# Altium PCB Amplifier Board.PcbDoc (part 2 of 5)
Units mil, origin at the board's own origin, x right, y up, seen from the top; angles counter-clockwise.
Board outline 6000 x 4000 mil, 6 copper layers (Top Layer, GND, VCC, InternalPlane3, InternalPlane4, Bottom Layer); 880 components, 519 nets, 2020 pads, 372 vias.
Unrouted connection lines stored in the file: 585.
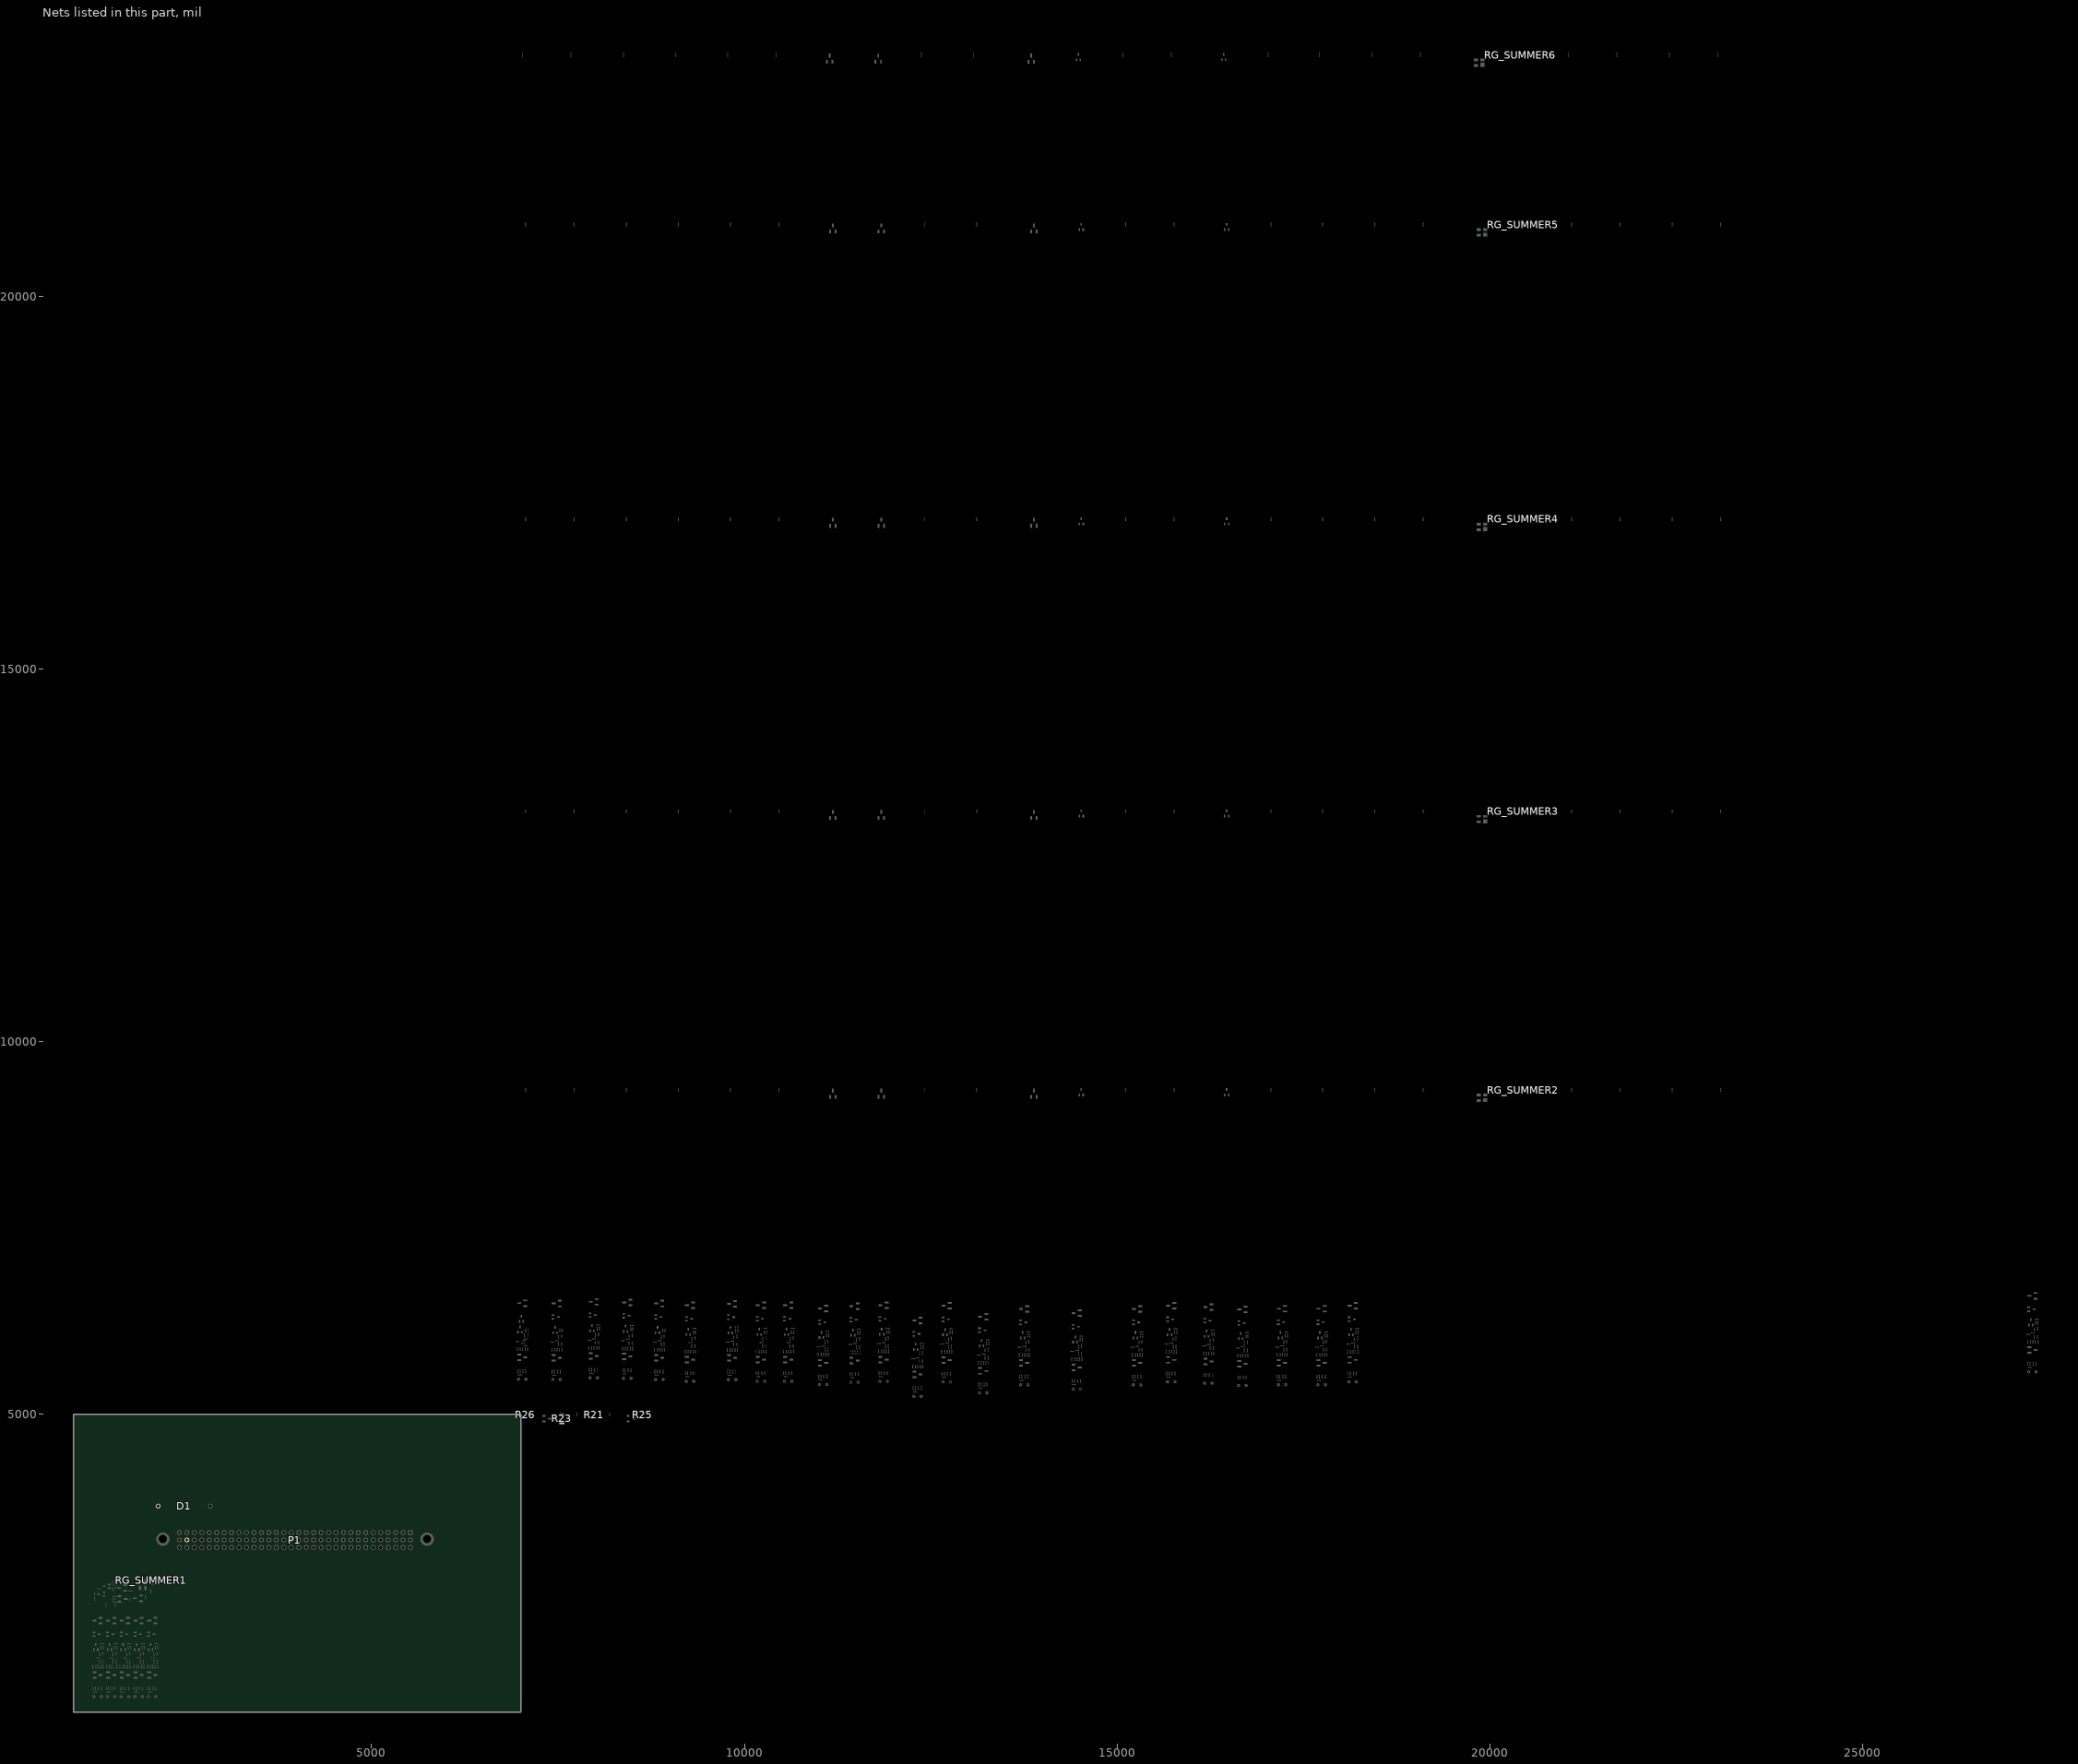
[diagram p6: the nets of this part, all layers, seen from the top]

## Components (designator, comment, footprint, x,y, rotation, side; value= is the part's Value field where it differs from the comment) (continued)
R2_AMP3 "Res2" RESC0603L 1715,1679 r90 top (schematic designator R2)
R2_AMP4 "Res2" RESC0603L 1899,1679 r90 top (schematic designator R2)
R2_AMP5 "Res2" RESC0603L 2082,1679 r90 top (schematic designator R2)
R2_AMP6 "Res2" RESC0603L 7030,5950 r0 top (schematic designator R2)
R2_AMP7 "Res2" RESC0603L 7507,5934 r90 top (schematic designator R2)
R2_AMP8 "Res2" RESC0603L 8004,5958 r90 top (schematic designator R2)
R2_AMP9 "Res2" RESC0603L 8455,5951 r90 top (schematic designator R2)
R2_AMP10 "Res2" RESC0603L 8884,5934 r90 top (schematic designator R2)
R2_AMP11 "Res2" RESC0603L 9296,5910 r90 top (schematic designator R2)
R2_AMP12 "Res2" RESC0603L 9860,5932 r90 top (schematic designator R2)
R2_AMP13 "Res2" RESC0603L 10247,5910 r90 top (schematic designator R2)
R2_AMP14 "Res2" RESC0603L 10613,5910 r90 top (schematic designator R2)
R2_AMP15 "Res2" RESC0603L 11081,5867 r90 top (schematic designator R2)
R2_AMP16 "Res2" RESC0603L 11503,5899 r90 top (schematic designator R2)
R2_AMP17 "Res2" RESC0603L 11891,5911 r90 top (schematic designator R2)
R2_AMP18 "Res2" RESC0603L 12347,5709 r90 top (schematic designator R2)
R2_AMP19 "Res2" RESC0603L 12739,5905 r90 top (schematic designator R2)
R2_AMP20 "Res2" RESC0603L 13229,5758 r90 top (schematic designator R2)
R2_AMP21 "Res2" RESC0603L 13779,5864 r90 top (schematic designator R2)
R2_AMP22 "Res2" RESC0603L 14484,5806 r90 top (schematic designator R2)
R2_AMP23 "Res2" RESC0603L 15293,5864 r90 top (schematic designator R2)
R2_AMP24 "Res2" RESC0603L 15751,5906 r90 top (schematic designator R2)
R2_AMP25 "Res2" RESC0603L 16250,5885 r90 top (schematic designator R2)
R2_AMP26 "Res2" RESC0603L 16707,5854 r90 top (schematic designator R2)
R2_AMP27 "Res2" RESC0603L 17237,5865 r90 top (schematic designator R2)
R2_AMP28 "Res2" RESC0603L 17768,5865 r90 top (schematic designator R2)
R2_AMP29 "Res2" RESC0603L 18185,5906 r90 top (schematic designator R2)
R2_AMP30 "Res2" RESC0603L 27303,6038 r90 top (schematic designator R2)
R3_AMP1 "Res2" RESC0603L 1264,1714 r0 top (schematic designator R3)
R3_AMP2 "Res2" RESC0603L 1447,1714 r0 top (schematic designator R3)
R3_AMP3 "Res2" RESC0603L 1630,1714 r0 top (schematic designator R3)
R3_AMP4 "Res2" RESC0603L 1814,1714 r0 top (schematic designator R3)
R3_AMP5 "Res2" RESC0603L 1997,1714 r0 top (schematic designator R3)
R3_AMP6 "Res2" RESC0603L 6960,5974 r0 top (schematic designator R3)
R3_AMP7 "Res2" RESC0603L 7422,5969 r0 top (schematic designator R3)
R3_AMP8 "Res2" RESC0603L 7919,5993 r0 top (schematic designator R3)
R3_AMP9 "Res2" RESC0603L 8370,5986 r0 top (schematic designator R3)
R3_AMP10 "Res2" RESC0603L 8799,5969 r0 top (schematic designator R3)
R3_AMP11 "Res2" RESC0603L 9211,5945 r0 top (schematic designator R3)
R3_AMP12 "Res2" RESC0603L 9775,5967 r0 top (schematic designator R3)
R3_AMP13 "Res2" RESC0603L 10162,5945 r0 top (schematic designator R3)
R3_AMP14 "Res2" RESC0603L 10528,5945 r0 top (schematic designator R3)
R3_AMP15 "Res2" RESC0603L 10996,5902 r0 top (schematic designator R3)
R3_AMP16 "Res2" RESC0603L 11418,5934 r0 top (schematic designator R3)
R3_AMP17 "Res2" RESC0603L 11806,5946 r0 top (schematic designator R3)
R3_AMP18 "Res2" RESC0603L 12262,5744 r0 top (schematic designator R3)
R3_AMP19 "Res2" RESC0603L 12654,5940 r0 top (schematic designator R3)
R3_AMP20 "Res2" RESC0603L 13144,5793 r0 top (schematic designator R3)
R3_AMP21 "Res2" RESC0603L 13694,5899 r0 top (schematic designator R3)
R3_AMP22 "Res2" RESC0603L 14399,5841 r0 top (schematic designator R3)
R3_AMP23 "Res2" RESC0603L 15208,5899 r0 top (schematic designator R3)
R3_AMP24 "Res2" RESC0603L 15666,5941 r0 top (schematic designator R3)
R3_AMP25 "Res2" RESC0603L 16165,5920 r0 top (schematic designator R3)
R3_AMP26 "Res2" RESC0603L 16622,5889 r0 top (schematic designator R3)
R3_AMP27 "Res2" RESC0603L 17152,5900 r0 top (schematic designator R3)
R3_AMP28 "Res2" RESC0603L 17683,5900 r0 top (schematic designator R3)
R3_AMP29 "Res2" RESC0603L 18100,5941 r0 top (schematic designator R3)
R3_AMP30 "Res2" RESC0603L 27218,6073 r0 top (schematic designator R3)
R4_AMP1 "Res2" RESC0603L 1329,1729 r0 top (schematic designator R4)
R4_AMP2 "Res2" RESC0603L 1512,1729 r0 top (schematic designator R4)
R4_AMP3 "Res2" RESC0603L 1695,1729 r0 top (schematic designator R4)
R4_AMP4 "Res2" RESC0603L 1879,1729 r0 top (schematic designator R4)
R4_AMP5 "Res2" RESC0603L 2062,1729 r0 top (schematic designator R4)
R4_AMP6 "Res2" RESC0603L 7040,5988 r0 top (schematic designator R4)
R4_AMP7 "Res2" RESC0603L 7487,5984 r0 top (schematic designator R4)
R4_AMP8 "Res2" RESC0603L 7984,6008 r0 top (schematic designator R4)
R4_AMP9 "Res2" RESC0603L 8435,6001 r0 top (schematic designator R4)
R4_AMP10 "Res2" RESC0603L 8864,5984 r0 top (schematic designator R4)
R4_AMP11 "Res2" RESC0603L 9276,5960 r0 top (schematic designator R4)
R4_AMP12 "Res2" RESC0603L 9840,5982 r0 top (schematic designator R4)
R4_AMP13 "Res2" RESC0603L 10227,5960 r0 top (schematic designator R4)
R4_AMP14 "Res2" RESC0603L 10593,5960 r0 top (schematic designator R4)
R4_AMP15 "Res2" RESC0603L 11061,5917 r0 top (schematic designator R4)
R4_AMP16 "Res2" RESC0603L 11483,5949 r0 top (schematic designator R4)
R4_AMP17 "Res2" RESC0603L 11871,5961 r0 top (schematic designator R4)
R4_AMP18 "Res2" RESC0603L 12327,5759 r0 top (schematic designator R4)
R4_AMP19 "Res2" RESC0603L 12719,5955 r0 top (schematic designator R4)
R4_AMP20 "Res2" RESC0603L 13209,5808 r0 top (schematic designator R4)
R4_AMP21 "Res2" RESC0603L 13759,5914 r0 top (schematic designator R4)
R4_AMP22 "Res2" RESC0603L 14464,5856 r0 top (schematic designator R4)
R4_AMP23 "Res2" RESC0603L 15273,5914 r0 top (schematic designator R4)
R4_AMP24 "Res2" RESC0603L 15731,5956 r0 top (schematic designator R4)
R4_AMP25 "Res2" RESC0603L 16230,5935 r0 top (schematic designator R4)
R4_AMP26 "Res2" RESC0603L 16687,5904 r0 top (schematic designator R4)
R4_AMP27 "Res2" RESC0603L 17217,5915 r0 top (schematic designator R4)
R4_AMP28 "Res2" RESC0603L 17748,5915 r0 top (schematic designator R4)
R4_AMP29 "Res2" RESC0603L 18165,5956 r0 top (schematic designator R4)
R4_AMP30 "Res2" RESC0603L 27283,6088 r0 top (schematic designator R4)
R5_AMP1 "Res2" RESC0603L 1349,1779 r270 top (schematic designator R5)
R5_AMP2 "Res2" RESC0603L 1532,1779 r270 top (schematic designator R5)
R5_AMP3 "Res2" RESC0603L 1715,1779 r270 top (schematic designator R5)
R5_AMP4 "Res2" RESC0603L 1899,1779 r270 top (schematic designator R5)
R5_AMP5 "Res2" RESC0603L 2082,1779 r270 top (schematic designator R5)
R5_AMP6 "Res2" RESC0603L 7065,6013 r0 top (schematic designator R5)
R5_AMP7 "Res2" RESC0603L 7507,6034 r270 top (schematic designator R5)
R5_AMP8 "Res2" RESC0603L 8004,6058 r270 top (schematic designator R5)
R5_AMP9 "Res2" RESC0603L 8455,6051 r270 top (schematic designator R5)
R5_AMP10 "Res2" RESC0603L 8884,6034 r270 top (schematic designator R5)
R5_AMP11 "Res2" RESC0603L 9296,6010 r270 top (schematic designator R5)
R5_AMP12 "Res2" RESC0603L 9860,6032 r270 top (schematic designator R5)
R5_AMP13 "Res2" RESC0603L 10247,6010 r270 top (schematic designator R5)
R5_AMP14 "Res2" RESC0603L 10613,6010 r270 top (schematic designator R5)
R5_AMP15 "Res2" RESC0603L 11081,5967 r270 top (schematic designator R5)
R5_AMP16 "Res2" RESC0603L 11503,5999 r270 top (schematic designator R5)
R5_AMP17 "Res2" RESC0603L 11891,6011 r270 top (schematic designator R5)
R5_AMP18 "Res2" RESC0603L 12347,5809 r270 top (schematic designator R5)
R5_AMP19 "Res2" RESC0603L 12739,6005 r270 top (schematic designator R5)
R5_AMP20 "Res2" RESC0603L 13229,5858 r270 top (schematic designator R5)
R5_AMP21 "Res2" RESC0603L 13779,5964 r270 top (schematic designator R5)
R5_AMP22 "Res2" RESC0603L 14484,5906 r270 top (schematic designator R5)
R5_AMP23 "Res2" RESC0603L 15293,5964 r270 top (schematic designator R5)
R5_AMP24 "Res2" RESC0603L 15751,6006 r270 top (schematic designator R5)
R5_AMP25 "Res2" RESC0603L 16250,5985 r270 top (schematic designator R5)
R5_AMP26 "Res2" RESC0603L 16707,5954 r270 top (schematic designator R5)
R5_AMP27 "Res2" RESC0603L 17237,5965 r270 top (schematic designator R5)
R5_AMP28 "Res2" RESC0603L 17768,5965 r270 top (schematic designator R5)
R5_AMP29 "Res2" RESC0603L 18185,6006 r270 top (schematic designator R5)
R5_AMP30 "Res2" RESC0603L 27303,6138 r270 top (schematic designator R5)
R6_AMP1 "Res2" RESC0603L 1363,1610 r90 top (schematic designator R6)
R6_AMP2 "Res2" RESC0603L 1546,1610 r90 top (schematic designator R6)
R6_AMP3 "Res2" RESC0603L 1729,1610 r90 top (schematic designator R6)
R6_AMP4 "Res2" RESC0603L 1913,1610 r90 top (schematic designator R6)
R6_AMP5 "Res2" RESC0603L 2096,1610 r90 top (schematic designator R6)
R6_AMP6 "Res2" RESC0603L 7059,5870 r90 top (schematic designator R6)
R6_AMP7 "Res2" RESC0603L 7521,5865 r90 top (schematic designator R6)
R6_AMP8 "Res2" RESC0603L 8018,5889 r90 top (schematic designator R6)
R6_AMP9 "Res2" RESC0603L 8469,5882 r90 top (schematic designator R6)
R6_AMP10 "Res2" RESC0603L 8898,5865 r90 top (schematic designator R6)
R6_AMP11 "Res2" RESC0603L 9310,5841 r90 top (schematic designator R6)
R6_AMP12 "Res2" RESC0603L 9874,5863 r90 top (schematic designator R6)
R6_AMP13 "Res2" RESC0603L 10261,5841 r90 top (schematic designator R6)
R6_AMP14 "Res2" RESC0603L 10627,5841 r90 top (schematic designator R6)
R6_AMP15 "Res2" RESC0603L 11095,5798 r90 top (schematic designator R6)
R6_AMP16 "Res2" RESC0603L 11517,5830 r90 top (schematic designator R6)
R6_AMP17 "Res2" RESC0603L 11905,5842 r90 top (schematic designator R6)
R6_AMP18 "Res2" RESC0603L 12361,5640 r90 top (schematic designator R6)
R6_AMP19 "Res2" RESC0603L 12753,5836 r90 top (schematic designator R6)
R6_AMP20 "Res2" RESC0603L 13243,5689 r90 top (schematic designator R6)
R6_AMP21 "Res2" RESC0603L 13793,5795 r90 top (schematic designator R6)
R6_AMP22 "Res2" RESC0603L 14498,5737 r90 top (schematic designator R6)
R6_AMP23 "Res2" RESC0603L 15307,5795 r90 top (schematic designator R6)
R6_AMP24 "Res2" RESC0603L 15765,5837 r90 top (schematic designator R6)
R6_AMP25 "Res2" RESC0603L 16264,5816 r90 top (schematic designator R6)
R6_AMP26 "Res2" RESC0603L 16721,5785 r90 top (schematic designator R6)
R6_AMP27 "Res2" RESC0603L 17251,5796 r90 top (schematic designator R6)
R6_AMP28 "Res2" RESC0603L 17782,5796 r90 top (schematic designator R6)
R6_AMP29 "Res2" RESC0603L 18199,5837 r90 top (schematic designator R6)
R6_AMP30 "Res2" RESC0603L 27317,5969 r90 top (schematic designator R6)
R7_AMP1 "Res2" RESC0603L 1389,1789 r270 top (schematic designator R7)
R7_AMP2 "Res2" RESC0603L 1572,1789 r270 top (schematic designator R7)
R7_AMP3 "Res2" RESC0603L 1755,1789 r270 top (schematic designator R7)
R7_AMP4 "Res2" RESC0603L 1939,1789 r270 top (schematic designator R7)
R7_AMP5 "Res2" RESC0603L 2122,1789 r270 top (schematic designator R7)
R7_AMP6 "Res2" RESC0603L 7095,6058 r270 top (schematic designator R7)
R7_AMP7 "Res2" RESC0603L 7547,6044 r270 top (schematic designator R7)
R7_AMP8 "Res2" RESC0603L 8044,6068 r270 top (schematic designator R7)
R7_AMP9 "Res2" RESC0603L 8495,6061 r270 top (schematic designator R7)
R7_AMP10 "Res2" RESC0603L 8924,6044 r270 top (schematic designator R7)
R7_AMP11 "Res2" RESC0603L 9336,6020 r270 top (schematic designator R7)
R7_AMP12 "Res2" RESC0603L 9900,6042 r270 top (schematic designator R7)
R7_AMP13 "Res2" RESC0603L 10287,6020 r270 top (schematic designator R7)
R7_AMP14 "Res2" RESC0603L 10653,6020 r270 top (schematic designator R7)
R7_AMP15 "Res2" RESC0603L 11121,5977 r270 top (schematic designator R7)
R7_AMP16 "Res2" RESC0603L 11543,6009 r270 top (schematic designator R7)
R7_AMP17 "Res2" RESC0603L 11931,6021 r270 top (schematic designator R7)
R7_AMP18 "Res2" RESC0603L 12387,5819 r270 top (schematic designator R7)
R7_AMP19 "Res2" RESC0603L 12779,6015 r270 top (schematic designator R7)
R7_AMP20 "Res2" RESC0603L 13269,5868 r270 top (schematic designator R7)
R7_AMP21 "Res2" RESC0603L 13819,5974 r270 top (schematic designator R7)
R7_AMP22 "Res2" RESC0603L 14524,5916 r270 top (schematic designator R7)
R7_AMP23 "Res2" RESC0603L 15333,5974 r270 top (schematic designator R7)
R7_AMP24 "Res2" RESC0603L 15791,6016 r270 top (schematic designator R7)
R7_AMP25 "Res2" RESC0603L 16290,5995 r270 top (schematic designator R7)
R7_AMP26 "Res2" RESC0603L 16747,5964 r270 top (schematic designator R7)
R7_AMP27 "Res2" RESC0603L 17277,5975 r270 top (schematic designator R7)
R7_AMP28 "Res2" RESC0603L 17808,5975 r270 top (schematic designator R7)
R7_AMP29 "Res2" RESC0603L 18225,6016 r270 top (schematic designator R7)
R7_AMP30 "Res2" RESC0603L 27343,6148 r270 top (schematic designator R7)
R8_AMP1 "Res2" RESC0603L 1383,1919 r180 top (schematic designator R8)
R8_AMP2 "Res2" RESC0603L 1566,1919 r180 top (schematic designator R8)
R8_AMP3 "Res2" RESC0603L 1749,1919 r180 top (schematic designator R8)
R8_AMP4 "Res2" RESC0603L 1933,1919 r180 top (schematic designator R8)
R8_AMP5 "Res2" RESC0603L 2116,1919 r180 top (schematic designator R8)
R8_AMP6 "Res2" RESC0603L 7065,6123 r270 top (schematic designator R8)
R8_AMP7 "Res2" RESC0603L 7541,6174 r180 top (schematic designator R8)
R8_AMP8 "Res2" RESC0603L 8038,6198 r180 top (schematic designator R8)
R8_AMP9 "Res2" RESC0603L 8489,6191 r180 top (schematic designator R8)
R8_AMP10 "Res2" RESC0603L 8918,6174 r180 top (schematic designator R8)
R8_AMP11 "Res2" RESC0603L 9330,6150 r180 top (schematic designator R8)
R8_AMP12 "Res2" RESC0603L 9894,6172 r180 top (schematic designator R8)
R8_AMP13 "Res2" RESC0603L 10281,6150 r180 top (schematic designator R8)
R8_AMP14 "Res2" RESC0603L 10647,6150 r180 top (schematic designator R8)
R8_AMP15 "Res2" RESC0603L 11115,6107 r180 top (schematic designator R8)
R8_AMP16 "Res2" RESC0603L 11537,6139 r180 top (schematic designator R8)
R8_AMP17 "Res2" RESC0603L 11925,6151 r180 top (schematic designator R8)
R8_AMP18 "Res2" RESC0603L 12381,5949 r180 top (schematic designator R8)
R8_AMP19 "Res2" RESC0603L 12773,6145 r180 top (schematic designator R8)
R8_AMP20 "Res2" RESC0603L 13263,5998 r180 top (schematic designator R8)
R8_AMP21 "Res2" RESC0603L 13813,6104 r180 top (schematic designator R8)
R8_AMP22 "Res2" RESC0603L 14518,6046 r180 top (schematic designator R8)
R8_AMP23 "Res2" RESC0603L 15327,6104 r180 top (schematic designator R8)
R8_AMP24 "Res2" RESC0603L 15785,6146 r180 top (schematic designator R8)
R8_AMP25 "Res2" RESC0603L 16284,6125 r180 top (schematic designator R8)
R8_AMP26 "Res2" RESC0603L 16741,6094 r180 top (schematic designator R8)
R8_AMP27 "Res2" RESC0603L 17271,6105 r180 top (schematic designator R8)
R8_AMP28 "Res2" RESC0603L 17802,6105 r180 top (schematic designator R8)
R8_AMP29 "Res2" RESC0603L 18219,6146 r180 top (schematic designator R8)
R8_AMP30 "Res2" RESC0603L 27337,6278 r180 top (schematic designator R8)
R9_SUMMER1 "Res2" RESC0603L 1435,2440 r270 top (schematic designator R9)
R9_SUMMER2 "Res2" RESC0603L 7065,9350 r90 top (schematic designator R9)
R9_SUMMER3 "Res2" RESC0603L 7065,13090 r90 top (schematic designator R9)
R9_SUMMER4 "Res2" RESC0603L 7065,17010 r90 top (schematic designator R9)
R9_SUMMER5 "Res2" RESC0603L 7065,20960 r90 top (schematic designator R9)
R9_SUMMER6 "Res2" RESC0603L 7026,23238 r90 top (schematic designator R9)
R10_SUMMER1 "Res2" RESC0603L 2035,2625 r270 top (schematic designator R10)
R10_SUMMER2 "Res2" RESC0603L 23095,9350 r90 top (schematic designator R10)
R10_SUMMER3 "Res2" RESC0603L 23095,13090 r90 top (schematic designator R10)
R10_SUMMER4 "Res2" RESC0603L 23095,17010 r90 top (schematic designator R10)
R10_SUMMER5 "Res2" RESC0603L 23095,20960 r90 top (schematic designator R10)
R10_SUMMER6 "Res2" RESC0603L 23056,23238 r90 top (schematic designator R10)
R11_SUMMER1 "Res2" RESC0603L 1760,2505 r90 top (schematic designator R11)
R11_SUMMER2 "Res2" RESC0603L 17065,9350 r90 top (schematic designator R11)
R11_SUMMER3 "Res2" RESC0603L 17065,13090 r90 top (schematic designator R11)
R11_SUMMER4 "Res2" RESC0603L 17065,17010 r90 top (schematic designator R11)
R11_SUMMER5 "Res2" RESC0603L 17065,20960 r90 top (schematic designator R11)
R11_SUMMER6 "Res2" RESC0603L 17026,23238 r90 top (schematic designator R11)
R12_SUMMER1 "Res2" RESC0603L 1550,2485 r0 top (schematic designator R12)
R12_SUMMER2 "Res2" RESC0603L 7715,9350 r90 top (schematic designator R12)
R12_SUMMER3 "Res2" RESC0603L 7715,13090 r90 top (schematic designator R12)
R12_SUMMER4 "Res2" RESC0603L 7715,17010 r90 top (schematic designator R12)
R12_SUMMER5 "Res2" RESC0603L 7715,20960 r90 top (schematic designator R12)
R12_SUMMER6 "Res2" RESC0603L 7676,23238 r90 top (schematic designator R12)
R13_SUMMER1 "Res2" RESC0603L 1559,2747 r90 top (schematic designator R13)
R13_SUMMER2 "Res2" RESC0603L 17755,9350 r90 top (schematic designator R13)
R13_SUMMER3 "Res2" RESC0603L 17755,13090 r90 top (schematic designator R13)
R13_SUMMER4 "Res2" RESC0603L 17755,17010 r90 top (schematic designator R13)
R13_SUMMER5 "Res2" RESC0603L 17755,20960 r90 top (schematic designator R13)
R13_SUMMER6 "Res2" RESC0603L 17716,23238 r90 top (schematic designator R13)
R14_SUMMER1 "Res2" RESC0603L 1764,2702 r180 top (schematic designator R14)
R14_SUMMER2 "Res2" RESC0603L 9115,9350 r90 top (schematic designator R14)
R14_SUMMER3 "Res2" RESC0603L 9115,13090 r90 top (schematic designator R14)
R14_SUMMER4 "Res2" RESC0603L 9115,17010 r90 top (schematic designator R14)
R14_SUMMER5 "Res2" RESC0603L 9115,20960 r90 top (schematic designator R14)
R14_SUMMER6 "Res2" RESC0603L 9076,23238 r90 top (schematic designator R14)
R15_SUMMER1 "Res2" RESC0603L 1345,2655 r180 top (schematic designator R15)
R15_SUMMER2 "Res2" RESC0603L 19105,9350 r90 top (schematic designator R15)
R15_SUMMER3 "Res2" RESC0603L 19105,13090 r90 top (schematic designator R15)
R15_SUMMER4 "Res2" RESC0603L 19105,17010 r90 top (schematic designator R15)
R15_SUMMER5 "Res2" RESC0603L 19105,20960 r90 top (schematic designator R15)
R15_SUMMER6 "Res2" RESC0603L 19066,23238 r90 top (schematic designator R15)
R16_SUMMER1 "Res2" RESC0603L 1285,2585 r90 top (schematic designator R16)
R16_SUMMER2 "Res2" RESC0603L 21745,9350 r90 top (schematic designator R16)
R16_SUMMER3 "Res2" RESC0603L 21745,13090 r90 top (schematic designator R16)
R16_SUMMER4 "Res2" RESC0603L 21745,17010 r90 top (schematic designator R16)
R16_SUMMER5 "Res2" RESC0603L 21745,20960 r90 top (schematic designator R16)
R16_SUMMER6 "Res2" RESC0603L 21706,23238 r90 top (schematic designator R16)
R17_SUMMER1 "Res2" RESC0603L 1764,2627 r180 top (schematic designator R17)
R17_SUMMER2 "Res2" RESC0603L 8415,9350 r90 top (schematic designator R17)
R17_SUMMER3 "Res2" RESC0603L 8415,13090 r90 top (schematic designator R17)
R17_SUMMER4 "Res2" RESC0603L 8415,17010 r90 top (schematic designator R17)
R17_SUMMER5 "Res2" RESC0603L 8415,20960 r90 top (schematic designator R17)
R17_SUMMER6 "Res2" RESC0603L 8376,23238 r90 top (schematic designator R17)
R18_AMP1 "Res2" RESC0603L 1374,1317.78 r90 top (schematic designator R18)
R18_AMP2 "Res2" RESC0603L 1557,1317.78 r90 top (schematic designator R18)
R18_AMP3 "Res2" RESC0603L 1740,1317.78 r90 top (schematic designator R18)
R18_AMP4 "Res2" RESC0603L 1924,1317.78 r90 top (schematic designator R18)
R18_AMP5 "Res2" RESC0603L 2107,1317.78 r90 top (schematic designator R18)
R18_AMP6 "Res2" RESC0603L 7070,5577.78 r90 top (schematic designator R18)
R18_AMP7 "Res2" RESC0603L 7532,5572.78 r90 top (schematic designator R18)
R18_AMP8 "Res2" RESC0603L 8029,5596.78 r90 top (schematic designator R18)
R18_AMP9 "Res2" RESC0603L 8480,5589.78 r90 top (schematic designator R18)
R18_AMP10 "Res2" RESC0603L 8909,5572.78 r90 top (schematic designator R18)
R18_AMP11 "Res2" RESC0603L 9321,5548.78 r90 top (schematic designator R18)
R18_AMP12 "Res2" RESC0603L 9885,5570.78 r90 top (schematic designator R18)
R18_AMP13 "Res2" RESC0603L 10272,5548.78 r90 top (schematic designator R18)
R18_AMP14 "Res2" RESC0603L 10638,5548.78 r90 top (schematic designator R18)
R18_AMP15 "Res2" RESC0603L 11106,5505.78 r90 top (schematic designator R18)
R18_AMP16 "Res2" RESC0603L 11528,5537.78 r90 top (schematic designator R18)
R18_AMP17 "Res2" RESC0603L 11916,5549.78 r90 top (schematic designator R18)
R18_AMP18 "Res2" RESC0603L 12372,5347.78 r90 top (schematic designator R18)
R18_AMP19 "Res2" RESC0603L 12764,5543.78 r90 top (schematic designator R18)
R18_AMP20 "Res2" RESC0603L 13254,5396.78 r90 top (schematic designator R18)
R18_AMP21 "Res2" RESC0603L 13804,5502.78 r90 top (schematic designator R18)
R18_AMP22 "Res2" RESC0603L 14509,5444.78 r90 top (schematic designator R18)
R18_AMP23 "Res2" RESC0603L 15318,5502.78 r90 top (schematic designator R18)
R18_AMP24 "Res2" RESC0603L 15776,5544.78 r90 top (schematic designator R18)
R18_AMP25 "Res2" RESC0603L 16275,5523.78 r90 top (schematic designator R18)
R18_AMP26 "Res2" RESC0603L 16732,5492.78 r90 top (schematic designator R18)
R18_AMP27 "Res2" RESC0603L 17262,5503.78 r90 top (schematic designator R18)
R18_AMP28 "Res2" RESC0603L 17793,5503.78 r90 top (schematic designator R18)
R18_AMP29 "Res2" RESC0603L 18210,5544.78 r90 top (schematic designator R18)
R18_AMP30 "Res2" RESC0603L 27328,5676.78 r90 top (schematic designator R18)
R19_AMP1 "Res2" RESC0603L 1289,1269 r180 top (schematic designator R19)
R19_AMP2 "Res2" RESC0603L 1472,1269 r180 top (schematic designator R19)
R19_AMP3 "Res2" RESC0603L 1655,1269 r180 top (schematic designator R19)
R19_AMP4 "Res2" RESC0603L 1839,1269 r180 top (schematic designator R19)
R19_AMP5 "Res2" RESC0603L 2022,1269 r180 top (schematic designator R19)
R19_AMP6 "Res2" RESC0603L 6985,5529 r180 top (schematic designator R19)
R19_AMP7 "Res2" RESC0603L 7447,5524 r180 top (schematic designator R19)
R19_AMP8 "Res2" RESC0603L 7944,5548 r180 top (schematic designator R19)
R19_AMP9 "Res2" RESC0603L 8395,5541 r180 top (schematic designator R19)
R19_AMP10 "Res2" RESC0603L 8824,5524 r180 top (schematic designator R19)
R19_AMP11 "Res2" RESC0603L 9236,5500 r180 top (schematic designator R19)
R19_AMP12 "Res2" RESC0603L 9800,5522 r180 top (schematic designator R19)
R19_AMP13 "Res2" RESC0603L 10187,5500 r180 top (schematic designator R19)
R19_AMP14 "Res2" RESC0603L 10553,5500 r180 top (schematic designator R19)
R19_AMP15 "Res2" RESC0603L 11021,5457 r180 top (schematic designator R19)
R19_AMP16 "Res2" RESC0603L 11443,5489 r180 top (schematic designator R19)
R19_AMP17 "Res2" RESC0603L 11831,5501 r180 top (schematic designator R19)
R19_AMP18 "Res2" RESC0603L 12287,5299 r180 top (schematic designator R19)
R19_AMP19 "Res2" RESC0603L 12679,5495 r180 top (schematic designator R19)
R19_AMP20 "Res2" RESC0603L 13169,5348 r180 top (schematic designator R19)
R19_AMP21 "Res2" RESC0603L 13719,5454 r180 top (schematic designator R19)
R19_AMP22 "Res2" RESC0603L 14424,5396 r180 top (schematic designator R19)
R19_AMP23 "Res2" RESC0603L 15233,5454 r180 top (schematic designator R19)
R19_AMP24 "Res2" RESC0603L 15691,5496 r180 top (schematic designator R19)
R19_AMP25 "Res2" RESC0603L 16190,5475 r180 top (schematic designator R19)
R19_AMP26 "Res2" RESC0603L 16647,5444 r180 top (schematic designator R19)
R19_AMP27 "Res2" RESC0603L 17177,5455 r180 top (schematic designator R19)
R19_AMP28 "Res2" RESC0603L 17708,5455 r180 top (schematic designator R19)
R19_AMP29 "Res2" RESC0603L 18125,5496 r180 top (schematic designator R19)
R19_AMP30 "Res2" RESC0603L 27243,5628 r180 top (schematic designator R19)
R20_AMP1 "Res2" RESC0603L 1389,1679 r90 top (schematic designator R20)
R20_AMP2 "Res2" RESC0603L 1572,1679 r90 top (schematic designator R20)
R20_AMP3 "Res2" RESC0603L 1755,1679 r90 top (schematic designator R20)
R20_AMP4 "Res2" RESC0603L 1939,1679 r90 top (schematic designator R20)
R20_AMP5 "Res2" RESC0603L 2122,1679 r90 top (schematic designator R20)
R20_AMP6 "Res2" RESC0603L 7071.22,5915 r180 top (schematic designator R20)
R20_AMP7 "Res2" RESC0603L 7547,5934 r90 top (schematic designator R20)
R20_AMP8 "Res2" RESC0603L 8044,5958 r90 top (schematic designator R20)
R20_AMP9 "Res2" RESC0603L 8495,5951 r90 top (schematic designator R20)
R20_AMP10 "Res2" RESC0603L 8924,5934 r90 top (schematic designator R20)
R20_AMP11 "Res2" RESC0603L 9336,5910 r90 top (schematic designator R20)
R20_AMP12 "Res2" RESC0603L 9900,5932 r90 top (schematic designator R20)
R20_AMP13 "Res2" RESC0603L 10287,5910 r90 top (schematic designator R20)
R20_AMP14 "Res2" RESC0603L 10653,5910 r90 top (schematic designator R20)
R20_AMP15 "Res2" RESC0603L 11121,5867 r90 top (schematic designator R20)
R20_AMP16 "Res2" RESC0603L 11543,5899 r90 top (schematic designator R20)
R20_AMP17 "Res2" RESC0603L 11931,5911 r90 top (schematic designator R20)
R20_AMP18 "Res2" RESC0603L 12387,5709 r90 top (schematic designator R20)
R20_AMP19 "Res2" RESC0603L 12779,5905 r90 top (schematic designator R20)
R20_AMP20 "Res2" RESC0603L 13269,5758 r90 top (schematic designator R20)
R20_AMP21 "Res2" RESC0603L 13819,5864 r90 top (schematic designator R20)
R20_AMP22 "Res2" RESC0603L 14524,5806 r90 top (schematic designator R20)
R20_AMP23 "Res2" RESC0603L 15333,5864 r90 top (schematic designator R20)
R20_AMP24 "Res2" RESC0603L 15791,5906 r90 top (schematic designator R20)
R20_AMP25 "Res2" RESC0603L 16290,5885 r90 top (schematic designator R20)
R20_AMP26 "Res2" RESC0603L 16747,5854 r90 top (schematic designator R20)
R20_AMP27 "Res2" RESC0603L 17277,5865 r90 top (schematic designator R20)
R20_AMP28 "Res2" RESC0603L 17808,5865 r90 top (schematic designator R20)
R20_AMP29 "Res2" RESC0603L 18225,5906 r90 top (schematic designator R20)
R20_AMP30 "Res2" RESC0603L 27343,6038 r90 top (schematic designator R20)
R21 "Res2" RESC0603L 7985,4995 r90 top
R22 "Res2" RESC0603L 8195,4995 r90 top
R23 "Res2" RESC3216L 7555,4940 r90 top
R24 "Res2" RESC0603L 7755,4995 r90 top
R25 "Res2" RESC0603L 8635,4995 r90 top
R26 "Res2" RESC0603L 7065,4995 r90 top
RBi_AMP1 "Res2" RESC0603L 1299,1610 r270 top (schematic designator RBi)
RBi_AMP2 "Res2" RESC0603L 1482,1610 r270 top (schematic designator RBi)
RBi_AMP3 "Res2" RESC0603L 1665,1610 r270 top (schematic designator RBi)
RBi_AMP4 "Res2" RESC0603L 1849,1610 r270 top (schematic designator RBi)
RBi_AMP5 "Res2" RESC0603L 2032,1610 r270 top (schematic designator RBi)
RBi_AMP6 "Res2" RESC0603L 6995,5870 r270 top (schematic designator RBi)
RBi_AMP7 "Res2" RESC0603L 7457,5865 r270 top (schematic designator RBi)
RBi_AMP8 "Res2" RESC0603L 7954,5889 r270 top (schematic designator RBi)
RBi_AMP9 "Res2" RESC0603L 8405,5882 r270 top (schematic designator RBi)
RBi_AMP10 "Res2" RESC0603L 8834,5865 r270 top (schematic designator RBi)
RBi_AMP11 "Res2" RESC0603L 9246,5841 r270 top (schematic designator RBi)
RBi_AMP12 "Res2" RESC0603L 9810,5863 r270 top (schematic designator RBi)
RBi_AMP13 "Res2" RESC0603L 10197,5841 r270 top (schematic designator RBi)
RBi_AMP14 "Res2" RESC0603L 10563,5841 r270 top (schematic designator RBi)
RBi_AMP15 "Res2" RESC0603L 11031,5798 r270 top (schematic designator RBi)
RBi_AMP16 "Res2" RESC0603L 11453,5830 r270 top (schematic designator RBi)
RBi_AMP17 "Res2" RESC0603L 11841,5842 r270 top (schematic designator RBi)
RBi_AMP18 "Res2" RESC0603L 12297,5640 r270 top (schematic designator RBi)
RBi_AMP19 "Res2" RESC0603L 12689,5836 r270 top (schematic designator RBi)
RBi_AMP20 "Res2" RESC0603L 13179,5689 r270 top (schematic designator RBi)
RBi_AMP21 "Res2" RESC0603L 13729,5795 r270 top (schematic designator RBi)
RBi_AMP22 "Res2" RESC0603L 14434,5737 r270 top (schematic designator RBi)
RBi_AMP23 "Res2" RESC0603L 15243,5795 r270 top (schematic designator RBi)
RBi_AMP24 "Res2" RESC0603L 15701,5837 r270 top (schematic designator RBi)
RBi_AMP25 "Res2" RESC0603L 16200,5816 r270 top (schematic designator RBi)
RBi_AMP26 "Res2" RESC0603L 16657,5785 r270 top (schematic designator RBi)
RBi_AMP27 "Res2" RESC0603L 17187,5796 r270 top (schematic designator RBi)
RBi_AMP28 "Res2" RESC0603L 17718,5796 r270 top (schematic designator RBi)
RBi_AMP29 "Res2" RESC0603L 18135,5837 r270 top (schematic designator RBi)
RBi_AMP30 "Res2" RESC0603L 27253,5969 r270 top (schematic designator RBi)
RBi_SUMMER1 "Res2" RESC0603L 1550,2520 r0 top (schematic designator RBi)
RBi_SUMMER2 "Res2" RESC0603L 12415,9350 r90 top (schematic designator RBi)
RBi_SUMMER3 "Res2" RESC0603L 12415,13090 r90 top (schematic designator RBi)
RBi_SUMMER4 "Res2" RESC0603L 12415,17010 r90 top (schematic designator RBi)
RBi_SUMMER5 "Res2" RESC0603L 12415,20960 r90 top (schematic designator RBi)
RBi_SUMMER6 "Res2" RESC0603L 12376,23238 r90 top (schematic designator RBi)
RC_SUMMER1 "Res2" RESC0603L 1524,2652 r90 top (schematic designator RC)
RC_SUMMER2 "Res2" RESC0603L 9815,9350 r90 top (schematic designator RC)
RC_SUMMER3 "Res2" RESC0603L 9815,13090 r90 top (schematic designator RC)
RC_SUMMER4 "Res2" RESC0603L 9815,17010 r90 top (schematic designator RC)
RC_SUMMER5 "Res2" RESC0603L 9815,20960 r90 top (schematic designator RC)
RC_SUMMER6 "Res2" RESC0603L 9776,23238 r90 top (schematic designator RC)
RD_SUMMER1 "Res2" RESC0603L 1524,2737 r90 top (schematic designator RD)
RD_SUMMER2 "Res2" RESC0603L 18455,9350 r90 top (schematic designator RD)
RD_SUMMER3 "Res2" RESC0603L 18455,13090 r90 top (schematic designator RD)
RD_SUMMER4 "Res2" RESC0603L 18455,17010 r90 top (schematic designator RD)
RD_SUMMER5 "Res2" RESC0603L 18455,20960 r90 top (schematic designator RD)
RD_SUMMER6 "Res2" RESC0603L 18416,23238 r90 top (schematic designator RD)
RG_SUMMER1 "Res2" RESC0603L 2040,2770 r90 top (schematic designator RG)
RG_SUMMER2 "Res2" RESC0603L 20445,9350 r90 top (schematic designator RG)
RG_SUMMER3 "Res2" RESC0603L 20445,13090 r90 top (schematic designator RG)
RG_SUMMER4 "Res2" RESC0603L 20445,17010 r90 top (schematic designator RG)
RG_SUMMER5 "Res2" RESC0603L 20445,20960 r90 top (schematic designator RG)
RG_SUMMER6 "Res2" RESC0603L 20406,23238 r90 top (schematic designator RG)
SIPM_AMP1 "Photo Sen" "Photonique SiPM" 1324,1159 r0 top (schematic designator SIPM)
SIPM_AMP2 "Photo Sen" "Photonique SiPM" 1507,1159 r0 top (schematic designator SIPM)
SIPM_AMP3 "Photo Sen" "Photonique SiPM" 1690,1159 r0 top (schematic designator SIPM)
SIPM_AMP4 "Photo Sen" "Photonique SiPM" 1874,1159 r0 top (schematic designator SIPM)
SIPM_AMP5 "Photo Sen" "Photonique SiPM" 2057,1159 r0 top (schematic designator SIPM)
SIPM_AMP6 "Photo Sen" "Photonique SiPM" 7020,5419 r0 top (schematic designator SIPM)
SIPM_AMP7 "Photo Sen" "Photonique SiPM" 7482,5414 r0 top (schematic designator SIPM)
SIPM_AMP8 "Photo Sen" "Photonique SiPM" 7979,5438 r0 top (schematic designator SIPM)
SIPM_AMP9 "Photo Sen" "Photonique SiPM" 8430,5431 r0 top (schematic designator SIPM)
SIPM_AMP10 "Photo Sen" "Photonique SiPM" 8859,5414 r0 top (schematic designator SIPM)
SIPM_AMP11 "Photo Sen" "Photonique SiPM" 9271,5390 r0 top (schematic designator SIPM)
SIPM_AMP12 "Photo Sen" "Photonique SiPM" 9835,5412 r0 top (schematic designator SIPM)
SIPM_AMP13 "Photo Sen" "Photonique SiPM" 10222,5390 r0 top (schematic designator SIPM)
SIPM_AMP14 "Photo Sen" "Photonique SiPM" 10588,5390 r0 top (schematic designator SIPM)
SIPM_AMP15 "Photo Sen" "Photonique SiPM" 11056,5347 r0 top (schematic designator SIPM)
SIPM_AMP16 "Photo Sen" "Photonique SiPM" 11478,5379 r0 top (schematic designator SIPM)
SIPM_AMP17 "Photo Sen" "Photonique SiPM" 11866,5391 r0 top (schematic designator SIPM)
SIPM_AMP18 "Photo Sen" "Photonique SiPM" 12322,5189 r0 top (schematic designator SIPM)
SIPM_AMP19 "Photo Sen" "Photonique SiPM" 12714,5385 r0 top (schematic designator SIPM)
SIPM_AMP20 "Photo Sen" "Photonique SiPM" 13204,5238 r0 top (schematic designator SIPM)
SIPM_AMP21 "Photo Sen" "Photonique SiPM" 13754,5344 r0 top (schematic designator SIPM)
SIPM_AMP22 "Photo Sen" "Photonique SiPM" 14459,5286 r0 top (schematic designator SIPM)
SIPM_AMP23 "Photo Sen" "Photonique SiPM" 15268,5344 r0 top (schematic designator SIPM)
SIPM_AMP24 "Photo Sen" "Photonique SiPM" 15726,5386 r0 top (schematic designator SIPM)
SIPM_AMP25 "Photo Sen" "Photonique SiPM" 16225,5365 r0 top (schematic designator SIPM)
SIPM_AMP26 "Photo Sen" "Photonique SiPM" 16682,5334 r0 top (schematic designator SIPM)
SIPM_AMP27 "Photo Sen" "Photonique SiPM" 17212,5345 r0 top (schematic designator SIPM)
SIPM_AMP28 "Photo Sen" "Photonique SiPM" 17743,5345 r0 top (schematic designator SIPM)
SIPM_AMP29 "Photo Sen" "Photonique SiPM" 18160,5386 r0 top (schematic designator SIPM)
SIPM_AMP30 "Photo Sen" "Photonique SiPM" 27278,5518 r0 top (schematic designator SIPM)
VR1 "Volt Reg" SOT23_L 8480,4940 r0 top
VR2 "Volt Reg" SOT23_L 7350,4940 r0 top

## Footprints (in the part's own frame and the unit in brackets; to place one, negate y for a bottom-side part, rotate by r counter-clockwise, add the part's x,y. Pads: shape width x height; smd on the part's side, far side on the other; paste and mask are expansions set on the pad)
DIODE-0.7 [mm] "Zener Diode; 2 Leads"
  round 1.65 hole 1: 1(-8.89,0) 2(8.89,0)
  silkscreen extent -7.37,-2.54 7.37,2.54
EURO2.54-2V96 [mm] "Connector; DIN 41612, Type C, Thru-Hole; Rows a+b+c, 96 Position; Vertical"
  round 4.6 hole 2.8: 33(-45,-0.3) 34(45,-0.3)
  rect 1.65x1.65 hole 1: A1(-39.37,-2.54)
  round 1.65 hole 1: A2(-36.83,-2.54) A3(-34.29,-2.54) A4(-31.75,-2.54) A5(-29.21,-2.54) A6(-26.67,-2.54) A7(-24.13,-2.54) A8(-21.59,-2.54) A9(-19.05,-2.54) A10(-16.51,-2.54) A11(-13.97,-2.54) A12(-11.43,-2.54) A13(-8.89,-2.54) A14(-6.35,-2.54) A15(-3.81,-2.54) A16(-1.27,-2.54) A17(1.27,-2.54) A18(3.81,-2.54) A19(6.35,-2.54) A20(8.89,-2.54) A21(11.43,-2.54) A22(13.97,-2.54) A23(16.51,-2.54) A24(19.05,-2.54) A25(21.59,-2.54) A26(24.13,-2.54) A27(26.67,-2.54) A28(29.21,-2.54) A29(31.75,-2.54) A30(34.29,-2.54) A31(36.83,-2.54) A32(39.37,-2.54) B1(-39.37,0) B2(-36.83,0) B3(-34.29,0) B4(-31.75,0) B5(-29.21,0) B6(-26.67,0) B7(-24.13,0) B8(-21.59,0) B9(-19.05,0) B10(-16.51,0) B11(-13.97,0) B12(-11.43,0) B13(-8.89,0) B14(-6.35,0) B15(-3.81,0) B16(-1.27,0) B17(1.27,0) B18(3.81,0) B19(6.35,0) B20(8.89,0) B21(11.43,0) B22(13.97,0) B23(16.51,0) B24(19.05,0) B25(21.59,0) B26(24.13,0) B27(26.67,0) B28(29.21,0) B29(31.75,0) B30(34.29,0) B31(36.83,0) B32(39.37,0) C1(-39.37,2.54) C2(-36.83,2.54) C3(-34.29,2.54) C4(-31.75,2.54) C5(-29.21,2.54) C6(-26.67,2.54) C7(-24.13,2.54) C8(-21.59,2.54) C9(-19.05,2.54) C10(-16.51,2.54) C11(-13.97,2.54) C12(-11.43,2.54) C13(-8.89,2.54) C14(-6.35,2.54) C15(-3.81,2.54) C16(-1.27,2.54) C17(1.27,2.54) C18(3.81,2.54) C19(6.35,2.54) C20(8.89,2.54) C21(11.43,2.54) C22(13.97,2.54) C23(16.51,2.54) C24(19.05,2.54) C25(21.59,2.54) C26(24.13,2.54) C27(26.67,2.54) C28(29.21,2.54) C29(31.75,2.54) C30(34.29,2.54) C31(36.83,2.54) C32(39.37,2.54)
  silkscreen extent -47.5,-5.55 47.5,5.55
"Photonique SiPM" [mil]
  round 40 hole 19.7: 1(-50,50) 2(50,50)
RESC0603L [mm] "Chip Resistor, Body 0.6x0.3mm, IPC High Density"
  rect 0.5x0.3 smd: 1(-0.35,0) 2(0.35,0)
  body extent -0.32,-0.17 0.32,0.17, height 0.3
RESC3216L [mm] "Chip Resistor, Body 3.2x1.6mm, IPC High Density"
  rect 1.1x1.7 smd: 1(-1.35,0) 2(1.35,0)
  silkscreen extent -0.4,-0.75 0.4,0.75, body extent -1.68,-0.87 1.68,0.87, height 0.71
SOT23_L [mm] "SOT23, 3-Leads, Body 2.9x1.3mm, Pitch 0.95mm, Lead Span 2.3mm, IPC High Density"
  rect 1x0.6 smd: 1(-1,0.95) 2(-1,-0.95) 3(1,0)
  silkscreen extent -1.12,-1.5 0.7,1.92, body extent -0.7,-1.5 0.7,1.5, height 1.1
SOT23_N [mm] "SOT23, 3-Leads, Body 2.9x1.3mm, Pitch 0.95mm, Lead Span 2.3mm, IPC Medium Density"
  rect 1.3x0.6 smd: 1(-1.05,0.95) 2(-1.05,-0.95) 3(1.05,0)
  silkscreen extent -1.17,-1.5 0.7,1.92, body extent -0.7,-1.5 0.7,1.5, height 1.1
SOT323_L [mm] "SOT323, 3-Leads, Body 2.0x1.3mm, Pitch 0.65mm, Lead Span 2.1mm, IPC High Density"
  rect 0.9x0.5 smd: 1(-0.9,0.65) 2(-0.9,-0.65) 3(0.9,0)
  silkscreen extent -1.02,-1.1 0.7,1.57, body extent -0.7,-1.1 0.7,1.1, height 1.1
SOT-143 [mm] "SOT-143; 4 Leads; Body 3 x 2.6 mm, inc. leads (LxW max)"
  rect 1.35x1.35 smd: 1(-0.75,-1.1)
  rect 0.9x1.35 smd: 2(0.95,-1.1) 3(0.95,1.1) 4(-0.95,1.1)
  silkscreen extent -1.88,-2.22 1.75,0.7

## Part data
C1_AMP1 C1_AMP2 C1_AMP3 C1_AMP4 C1_AMP5 C1_AMP6 C1_AMP7 C1_AMP8 C1_AMP9 C1_AMP10 C1_AMP11 C1_AMP12 C1_AMP13 C1_AMP14 C1_AMP15 C1_AMP16 C1_AMP17 C1_AMP18 C1_AMP19 C1_AMP20 C1_AMP21 C1_AMP22 C1_AMP23 C1_AMP24 C1_AMP25 C1_AMP26 C1_AMP27 C1_AMP28 C1_AMP29 C1_AMP30 C2_AMP1 C2_AMP2 C2_AMP3 C2_AMP4 C2_AMP5 C2_AMP6 C2_AMP7 C2_AMP8 C2_AMP9 C2_AMP10 C2_AMP11 C2_AMP12 C2_AMP13 C2_AMP14 C2_AMP15 C2_AMP16 C2_AMP17 C2_AMP18 C2_AMP19 C2_AMP20 C2_AMP21 C2_AMP22 C2_AMP23 C2_AMP24 C2_AMP25 C2_AMP26 C2_AMP27 C2_AMP28 C2_AMP29 C2_AMP30 C3_AMP1 C3_AMP2 C3_AMP3 C3_AMP4 C3_AMP5 C3_AMP6 C3_AMP7 C3_AMP8 C3_AMP9 C3_AMP10 C3_AMP11 C3_AMP12 C3_AMP13 C3_AMP14 C3_AMP15 C3_AMP16 C3_AMP17 C3_AMP18 C3_AMP19 C3_AMP20 C3_AMP21 C3_AMP22 C3_AMP23 C3_AMP24 C3_AMP25 C3_AMP26 C3_AMP27 C3_AMP28 C3_AMP29 C3_AMP30 C4_AMP1 C4_AMP2 C4_AMP3 C4_AMP4 C4_AMP5 C4_AMP6 C4_AMP7 C4_AMP8 C4_AMP9 C4_AMP10 C4_AMP11 C4_AMP12 C4_AMP13 C4_AMP14 C4_AMP15 C4_AMP16 C4_AMP17 C4_AMP18 C4_AMP19 C4_AMP20 C4_AMP21 C4_AMP22 C4_AMP23 C4_AMP24 C4_AMP25 C4_AMP26 C4_AMP27 C4_AMP28 C4_AMP29 C4_AMP30 C5_AMP1 C5_AMP2 C5_AMP3 C5_AMP4 C5_AMP5 C5_AMP6 C5_AMP7 C5_AMP8 C5_AMP9 C5_AMP10 C5_AMP11 C5_AMP12 C5_AMP13 C5_AMP14 C5_AMP15 C5_AMP16 C5_AMP17 C5_AMP18 C5_AMP19 C5_AMP20 C5_AMP21 C5_AMP22 C5_AMP23 C5_AMP24 C5_AMP25 C5_AMP26 C5_AMP27 C5_AMP28 C5_AMP29 C5_AMP30 C5_SUMMER1 C5_SUMMER2 C5_SUMMER3 C5_SUMMER4 C5_SUMMER5 C5_SUMMER6 C6_AMP1 C6_AMP2 C6_AMP3 C6_AMP4 C6_AMP5 C6_AMP6 C6_AMP7 C6_AMP8 C6_AMP9 C6_AMP10 C6_AMP11 C6_AMP12 C6_AMP13 C6_AMP14 C6_AMP15 C6_AMP16 C6_AMP17 C6_AMP18 C6_AMP19 C6_AMP20 C6_AMP21 C6_AMP22 C6_AMP23 C6_AMP24 C6_AMP25 C6_AMP26 C6_AMP27 C6_AMP28 C6_AMP29 C6_AMP30 C7_SUMMER1 C7_SUMMER2 C7_SUMMER3 C7_SUMMER4 C7_SUMMER5 C7_SUMMER6 C8_SUMMER1 C8_SUMMER2 C8_SUMMER3 C8_SUMMER4 C8_SUMMER5 C8_SUMMER6 C9_SUMMER1 C9_SUMMER2 C9_SUMMER3 C9_SUMMER4 C9_SUMMER5 C9_SUMMER6 CBi_AMP1 CBi_AMP2 CBi_AMP3 CBi_AMP4 CBi_AMP5 CBi_AMP6 CBi_AMP7 CBi_AMP8 CBi_AMP9 CBi_AMP10 CBi_AMP11 CBi_AMP12 CBi_AMP13 CBi_AMP14 CBi_AMP15 CBi_AMP16 CBi_AMP17 CBi_AMP18 CBi_AMP19 CBi_AMP20 CBi_AMP21 CBi_AMP22 CBi_AMP23 CBi_AMP24 CBi_AMP25 CBi_AMP26 CBi_AMP27 CBi_AMP28 CBi_AMP29 CBi_AMP30 CBi_SUMMER1 CBi_SUMMER2 CBi_SUMMER3 CBi_SUMMER4 CBi_SUMMER5 CBi_SUMMER6 CG_SUMMER1 CG_SUMMER2 CG_SUMMER3 CG_SUMMER4 CG_SUMMER5 CG_SUMMER6: "Capacitor"
D1: library part "D Zener", "Zener Diode"
M1_SUMMER1 M1_SUMMER2 M1_SUMMER3 M1_SUMMER4 M1_SUMMER5 M1_SUMMER6: "N-Channel MOSFET"
Q0_AMP1 Q0_AMP2 Q0_AMP3 Q0_AMP4 Q0_AMP5 Q0_AMP6 Q0_AMP7 Q0_AMP8 Q0_AMP9 Q0_AMP10 Q0_AMP11 Q0_AMP12 Q0_AMP13 Q0_AMP14 Q0_AMP15 Q0_AMP16 Q0_AMP17 Q0_AMP18 Q0_AMP19 Q0_AMP20 Q0_AMP21 Q0_AMP22 Q0_AMP23 Q0_AMP24 Q0_AMP25 Q0_AMP26 Q0_AMP27 Q0_AMP28 Q0_AMP29 Q0_AMP30 Q1_AMP1 Q1_AMP2 Q1_AMP3 Q1_AMP4 Q1_AMP5 Q1_AMP6 Q1_AMP7 Q1_AMP8 Q1_AMP9 Q1_AMP10 Q1_AMP11 Q1_AMP12 Q1_AMP13 Q1_AMP14 Q1_AMP15 Q1_AMP16 Q1_AMP17 Q1_AMP18 Q1_AMP19 Q1_AMP20 Q1_AMP21 Q1_AMP22 Q1_AMP23 Q1_AMP24 Q1_AMP25 Q1_AMP26 Q1_AMP27 Q1_AMP28 Q1_AMP29 Q1_AMP30 Q4_SUMMER1 Q4_SUMMER2 Q4_SUMMER3 Q4_SUMMER4 Q4_SUMMER5 Q4_SUMMER6 Q5_SUMMER1 Q5_SUMMER2 Q5_SUMMER3 Q5_SUMMER4 Q5_SUMMER5 Q5_SUMMER6 Q8_SUMMER1 Q8_SUMMER2 Q8_SUMMER3 Q8_SUMMER4 Q8_SUMMER5 Q8_SUMMER6: library part BFR92A, "NPN 5 GHz Wideband Transistor"
Q2_AMP1 Q2_AMP2 Q2_AMP3 Q2_AMP4 Q2_AMP5 Q2_AMP6 Q2_AMP7 Q2_AMP8 Q2_AMP9 Q2_AMP10 Q2_AMP11 Q2_AMP12 Q2_AMP13 Q2_AMP14 Q2_AMP15 Q2_AMP16 Q2_AMP17 Q2_AMP18 Q2_AMP19 Q2_AMP20 Q2_AMP21 Q2_AMP22 Q2_AMP23 Q2_AMP24 Q2_AMP25 Q2_AMP26 Q2_AMP27 Q2_AMP28 Q2_AMP29 Q2_AMP30 Q3_AMP1 Q3_AMP2 Q3_AMP3 Q3_AMP4 Q3_AMP5 Q3_AMP6 Q3_AMP7 Q3_AMP8 Q3_AMP9 Q3_AMP10 Q3_AMP11 Q3_AMP12 Q3_AMP13 Q3_AMP14 Q3_AMP15 Q3_AMP16 Q3_AMP17 Q3_AMP18 Q3_AMP19 Q3_AMP20 Q3_AMP21 Q3_AMP22 Q3_AMP23 Q3_AMP24 Q3_AMP25 Q3_AMP26 Q3_AMP27 Q3_AMP28 Q3_AMP29 Q3_AMP30 Q6_SUMMER1 Q6_SUMMER2 Q6_SUMMER3 Q6_SUMMER4 Q6_SUMMER5 Q6_SUMMER6 Q7_SUMMER1 Q7_SUMMER2 Q7_SUMMER3 Q7_SUMMER4 Q7_SUMMER5 Q7_SUMMER6: library part PNP, "PNP Bipolar Transistor"
R1_AMP1 R1_AMP2 R1_AMP3 R1_AMP4 R1_AMP5 R1_AMP6 R1_AMP7 R1_AMP8 R1_AMP9 R1_AMP10 R1_AMP11 R1_AMP12 R1_AMP13 R1_AMP14 R1_AMP15 R1_AMP16 R1_AMP17 R1_AMP18 R1_AMP19 R1_AMP20 R1_AMP21 R1_AMP22 R1_AMP23 R1_AMP24 R1_AMP25 R1_AMP26 R1_AMP27 R1_AMP28 R1_AMP29 R1_AMP30 R2_AMP1 R2_AMP2 R2_AMP3 R2_AMP4 R2_AMP5 R2_AMP6 R2_AMP7 R2_AMP8 R2_AMP9 R2_AMP10 R2_AMP11 R2_AMP12 R2_AMP13 R2_AMP14 R2_AMP15 R2_AMP16 R2_AMP17 R2_AMP18 R2_AMP19 R2_AMP20 R2_AMP21 R2_AMP22 R2_AMP23 R2_AMP24 R2_AMP25 R2_AMP26 R2_AMP27 R2_AMP28 R2_AMP29 R2_AMP30 R3_AMP1 R3_AMP2 R3_AMP3 R3_AMP4 R3_AMP5 R3_AMP6 R3_AMP7 R3_AMP8 R3_AMP9 R3_AMP10 R3_AMP11 R3_AMP12 R3_AMP13 R3_AMP14 R3_AMP15 R3_AMP16 R3_AMP17 R3_AMP18 R3_AMP19 R3_AMP20 R3_AMP21 R3_AMP22 R3_AMP23 R3_AMP24 R3_AMP25 R3_AMP26 R3_AMP27 R3_AMP28 R3_AMP29 R3_AMP30 R4_AMP1 R4_AMP2 R4_AMP3 R4_AMP4 R4_AMP5 R4_AMP6 R4_AMP7 R4_AMP8 R4_AMP9 R4_AMP10 R4_AMP11 R4_AMP12 R4_AMP13 R4_AMP14 R4_AMP15 R4_AMP16 R4_AMP17 R4_AMP18 R4_AMP19 R4_AMP20 R4_AMP21 R4_AMP22 R4_AMP23 R4_AMP24 R4_AMP25 R4_AMP26 R4_AMP27 R4_AMP28 R4_AMP29 R4_AMP30 R5_AMP1 R5_AMP2 R5_AMP3 R5_AMP4 R5_AMP5 R5_AMP6 R5_AMP7 R5_AMP8 R5_AMP9 R5_AMP10 R5_AMP11 R5_AMP12 R5_AMP13 R5_AMP14 R5_AMP15 R5_AMP16 R5_AMP17 R5_AMP18 R5_AMP19 R5_AMP20 R5_AMP21 R5_AMP22 R5_AMP23 R5_AMP24 R5_AMP25 R5_AMP26 R5_AMP27 R5_AMP28 R5_AMP29 R5_AMP30 R6_AMP1 R6_AMP2 R6_AMP3 R6_AMP4 R6_AMP5 R6_AMP6 R6_AMP7 R6_AMP8 R6_AMP9 R6_AMP10 R6_AMP11 R6_AMP12 R6_AMP13 R6_AMP14 R6_AMP15 R6_AMP16 R6_AMP17 R6_AMP18 R6_AMP19 R6_AMP20 R6_AMP21 R6_AMP22 R6_AMP23 R6_AMP24 R6_AMP25 R6_AMP26 R6_AMP27 R6_AMP28 R6_AMP29 R6_AMP30 R7_AMP1 R7_AMP2 R7_AMP3 R7_AMP4 R7_AMP5 R7_AMP6 R7_AMP7 R7_AMP8 R7_AMP9 R7_AMP10 R7_AMP11 R7_AMP12 R7_AMP13 R7_AMP14 R7_AMP15 R7_AMP16 R7_AMP17 R7_AMP18 R7_AMP19 R7_AMP20 R7_AMP21 R7_AMP22 R7_AMP23 R7_AMP24 R7_AMP25 R7_AMP26 R7_AMP27 R7_AMP28 R7_AMP29 R7_AMP30 R8_AMP1 R8_AMP2 R8_AMP3 R8_AMP4 R8_AMP5 R8_AMP6 R8_AMP7 R8_AMP8 R8_AMP9 R8_AMP10 R8_AMP11 R8_AMP12 R8_AMP13 R8_AMP14 R8_AMP15 R8_AMP16 R8_AMP17 R8_AMP18 R8_AMP19 R8_AMP20 R8_AMP21 R8_AMP22 R8_AMP23 R8_AMP24 R8_AMP25 R8_AMP26 R8_AMP27 R8_AMP28 R8_AMP29 R8_AMP30 R9_SUMMER1 R9_SUMMER2 R9_SUMMER3 R9_SUMMER4 R9_SUMMER5 R9_SUMMER6 R10_SUMMER1 R10_SUMMER2 R10_SUMMER3 R10_SUMMER4 R10_SUMMER5 R10_SUMMER6 R11_SUMMER1 R11_SUMMER2 R11_SUMMER3 R11_SUMMER4 R11_SUMMER5 R11_SUMMER6 R12_SUMMER1 R12_SUMMER2 R12_SUMMER3 R12_SUMMER4 R12_SUMMER5 R12_SUMMER6 R13_SUMMER1 R13_SUMMER2 R13_SUMMER3 R13_SUMMER4 R13_SUMMER5 R13_SUMMER6 R14_SUMMER1 R14_SUMMER2 R14_SUMMER3 R14_SUMMER4 R14_SUMMER5 R14_SUMMER6 R15_SUMMER1 R15_SUMMER2 R15_SUMMER3 R15_SUMMER4 R15_SUMMER5 R15_SUMMER6 R16_SUMMER1 R16_SUMMER2 R16_SUMMER3 R16_SUMMER4 R16_SUMMER5 R16_SUMMER6 R17_SUMMER1 R17_SUMMER2 R17_SUMMER3 R17_SUMMER4 R17_SUMMER5 R17_SUMMER6 R18_AMP1 R18_AMP2 R18_AMP3 R18_AMP4 R18_AMP5 R18_AMP6 R18_AMP7 R18_AMP8 R18_AMP9 R18_AMP10 R18_AMP11 R18_AMP12 R18_AMP13 R18_AMP14 R18_AMP15 R18_AMP16 R18_AMP17 R18_AMP18 R18_AMP19 R18_AMP20 R18_AMP21 R18_AMP22 R18_AMP23 R18_AMP24 R18_AMP25 R18_AMP26 R18_AMP27 R18_AMP28 R18_AMP29 R18_AMP30 R19_AMP1 R19_AMP2 R19_AMP3 R19_AMP4 R19_AMP5 R19_AMP6 R19_AMP7 R19_AMP8 R19_AMP9 R19_AMP10 R19_AMP11 R19_AMP12 R19_AMP13 R19_AMP14 R19_AMP15 R19_AMP16 R19_AMP17 R19_AMP18 R19_AMP19 R19_AMP20 R19_AMP21 R19_AMP22 R19_AMP23 R19_AMP24 R19_AMP25 R19_AMP26 R19_AMP27 R19_AMP28 R19_AMP29 R19_AMP30 R20_AMP1 R20_AMP2 R20_AMP3 R20_AMP4 R20_AMP5 R20_AMP6 R20_AMP7 R20_AMP8 R20_AMP9 R20_AMP10 R20_AMP11 R20_AMP12 R20_AMP13 R20_AMP14 R20_AMP15 R20_AMP16 R20_AMP17 R20_AMP18 R20_AMP19 R20_AMP20 R20_AMP21 R20_AMP22 R20_AMP23 R20_AMP24 R20_AMP25 R20_AMP26 R20_AMP27 R20_AMP28 R20_AMP29 R20_AMP30 R21 R22 R23 R24 R25 R26 RBi_AMP1 RBi_AMP2 RBi_AMP3 RBi_AMP4 RBi_AMP5 RBi_AMP6 RBi_AMP7 RBi_AMP8 RBi_AMP9 RBi_AMP10 RBi_AMP11 RBi_AMP12 RBi_AMP13 RBi_AMP14 RBi_AMP15 RBi_AMP16 RBi_AMP17 RBi_AMP18 RBi_AMP19 RBi_AMP20 RBi_AMP21 RBi_AMP22 RBi_AMP23 RBi_AMP24 RBi_AMP25 RBi_AMP26 RBi_AMP27 RBi_AMP28 RBi_AMP29 RBi_AMP30 RBi_SUMMER1 RBi_SUMMER2 RBi_SUMMER3 RBi_SUMMER4 RBi_SUMMER5 RBi_SUMMER6 RC_SUMMER1 RC_SUMMER2 RC_SUMMER3 RC_SUMMER4 RC_SUMMER5 RC_SUMMER6 RD_SUMMER1 RD_SUMMER2 RD_SUMMER3 RD_SUMMER4 RD_SUMMER5 RD_SUMMER6 RG_SUMMER1 RG_SUMMER2 RG_SUMMER3 RG_SUMMER4 RG_SUMMER5 RG_SUMMER6: "Resistor"
SIPM_AMP1 SIPM_AMP2 SIPM_AMP3 SIPM_AMP4 SIPM_AMP5 SIPM_AMP6 SIPM_AMP7 SIPM_AMP8 SIPM_AMP9 SIPM_AMP10 SIPM_AMP11 SIPM_AMP12 SIPM_AMP13 SIPM_AMP14 SIPM_AMP15 SIPM_AMP16 SIPM_AMP17 SIPM_AMP18 SIPM_AMP19 SIPM_AMP20 SIPM_AMP21 SIPM_AMP22 SIPM_AMP23 SIPM_AMP24 SIPM_AMP25 SIPM_AMP26 SIPM_AMP27 SIPM_AMP28 SIPM_AMP29 SIPM_AMP30: "Photosensitive Diode"
VR1 VR2: "Voltage Regulator"

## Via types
v1: diameter 50, hole 28, Top Layer to Bottom Layer, 371 vias
v2: diameter 50, hole 28, Top Layer to Bottom Layer, tented top, 1 vias

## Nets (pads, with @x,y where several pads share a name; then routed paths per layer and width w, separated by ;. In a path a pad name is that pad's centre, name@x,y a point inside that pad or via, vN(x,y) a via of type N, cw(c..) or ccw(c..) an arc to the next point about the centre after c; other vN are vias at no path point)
+5V: R21.1 R23.1 R25.1 R26.1
GAINMODE: D1.2 P1.B31 RG_SUMMER1.2 RG_SUMMER2.2 RG_SUMMER3.2 RG_SUMMER4.2 RG_SUMMER5.2 RG_SUMMER6.2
